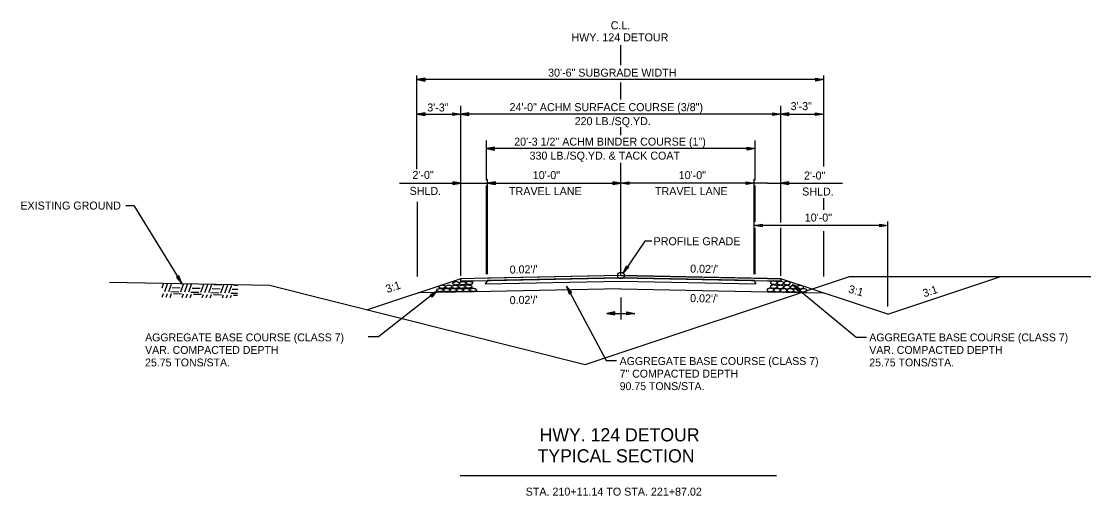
# Model space of a CAD drawing. Extents: x 1824008 to 1828864, y 689441 to 689870.
# Drawn here: x 1828742.7 to 1828822.3, y 689498 to 689533.6 of the extents above; entities that cross this region are included whole.
import ezdxf

# ---------------------------------------------------------------- set-up
doc = ezdxf.new("R2010")
doc.units = 0
for name, color, linetype in [('1', 7, 'Continuous'), ('19', 7, 'Continuous'), ('42', 7, 'Continuous'), ('Level 1', 7, 'Continuous'), ('R_Draft', 7, 'Continuous'), ('R_Horz Alg', 7, 'Continuous')]:
    doc.layers.add(name, color=color, linetype=linetype)

# ---------------------------------------------------------------- blocks, each defined once
blk = doc.blocks.new('ROCKS')
at = {"layer": '1'}
blk.add_spline([(0.013, 0.06), (0.053, 0.053), (0.107, 0.033), (0.133, 0.013), (0.133, -0.007), (0.12, -0.033), (0.107, -0.04), (0.073, -0.053), (0.033, -0.067), (0.013, -0.067), (-0.02, -0.06), (-0.06, -0.053), (-0.087, -0.047), (-0.113, -0.02), (-0.113, -0.007), (-0.107, 0.02), (-0.087, 0.033), (-0.067, 0.047), (-0.033, 0.053), (-0.02, 0.06), (0.013, 0.06)], degree=3, dxfattribs=at)

msp = doc.modelspace()

# ---------------------------------------------------------------- linework, layer by layer
at = {"layer": '1'}
for p, q in [((1828772.928, 689529.296), (1828772.328, 689529.191)), ((1828772.928, 689529.241), (1828772.488, 689529.206)), ((1828772.928, 689529.086), (1828772.928, 689529.296)), ((1828802.221, 689529.086), (1828802.221, 689529.296)), ((1828802.221, 689529.296), (1828802.821, 689529.191)), ((1828802.221, 689529.241), (1828802.661, 689529.206)), ((1828772.328, 689529.191), (1828772.928, 689529.086)), ((1828772.488, 689529.176), (1828772.928, 689529.136)), ((1828802.821, 689529.191), (1828802.221, 689529.086)), ((1828802.661, 689529.176), (1828802.221, 689529.136)), ((1828772.928, 689526.708), (1828772.328, 689526.603)), ((1828772.328, 689526.603), (1828772.928, 689526.498)), ((1828772.928, 689526.653), (1828772.488, 689526.618)), ((1828772.488, 689526.588), (1828772.928, 689526.548)), ((1828772.928, 689526.498), (1828772.928, 689526.708)), ((1828774.997, 689526.498), (1828774.997, 689526.708)), ((1828774.997, 689526.708), (1828775.597, 689526.603)), ((1828774.997, 689526.653), (1828775.437, 689526.618)), ((1828775.597, 689526.603), (1828774.997, 689526.498)), ((1828775.437, 689526.588), (1828774.997, 689526.548)), ((1828776.197, 689526.708), (1828775.597, 689526.603)), ((1828775.597, 689526.603), (1828776.197, 689526.498)), ((1828776.197, 689526.653), (1828775.757, 689526.618)), ((1828775.757, 689526.588), (1828776.197, 689526.548)), ((1828776.197, 689526.498), (1828776.197, 689526.708)), ((1828798.997, 689526.498), (1828798.997, 689526.708)), ((1828798.997, 689526.708), (1828799.597, 689526.603)), ((1828798.997, 689526.653), (1828799.437, 689526.618)), ((1828799.597, 689526.603), (1828798.997, 689526.498)), ((1828799.437, 689526.588), (1828798.997, 689526.548)), ((1828800.197, 689526.708), (1828799.597, 689526.603)), ((1828799.597, 689526.603), (1828800.197, 689526.498)), ((1828800.197, 689526.653), (1828799.757, 689526.618)), ((1828799.757, 689526.588), (1828800.197, 689526.548)), ((1828800.197, 689526.498), (1828800.197, 689526.708)), ((1828802.189, 689526.498), (1828802.189, 689526.708)), ((1828802.189, 689526.708), (1828802.789, 689526.603)), ((1828802.189, 689526.653), (1828802.629, 689526.618)), ((1828802.789, 689526.603), (1828802.189, 689526.498)), ((1828802.629, 689526.588), (1828802.189, 689526.548)), ((1828778.113, 689524.121), (1828777.513, 689524.016)), ((1828777.513, 689524.016), (1828778.113, 689523.911)), ((1828778.113, 689524.066), (1828777.673, 689524.031)), ((1828777.673, 689524.001), (1828778.113, 689523.961)), ((1828778.113, 689523.911), (1828778.113, 689524.121)), ((1828797.059, 689523.911), (1828797.059, 689524.121)), ((1828797.059, 689524.121), (1828797.659, 689524.016)), ((1828797.059, 689524.066), (1828797.499, 689524.031)), ((1828797.659, 689524.016), (1828797.059, 689523.911)), ((1828797.499, 689524.001), (1828797.059, 689523.961)), ((1828774.997, 689521.533), (1828774.997, 689521.323)), ((1828775.597, 689521.428), (1828774.997, 689521.533)), ((1828775.437, 689521.443), (1828774.997, 689521.478)), ((1828774.997, 689521.323), (1828775.597, 689521.428)), ((1828774.997, 689521.373), (1828775.437, 689521.413)), ((1828776.597, 689521.428), (1828787.597, 689521.428)), ((1828777.597, 689514.598), (1828777.597, 689521.728)), ((1828778.197, 689521.533), (1828777.597, 689521.428)), ((1828777.597, 689521.428), (1828787.597, 689521.428)), ((1828777.597, 689521.428), (1828778.197, 689521.323)), ((1828778.197, 689521.478), (1828777.757, 689521.443)), ((1828777.757, 689521.413), (1828778.197, 689521.373)), ((1828778.197, 689521.323), (1828778.197, 689521.533)), ((1828786.997, 689521.533), (1828786.997, 689521.323)), ((1828787.597, 689521.428), (1828786.997, 689521.533)), ((1828786.997, 689521.533), (1828786.997, 689521.323)), ((1828787.597, 689521.428), (1828786.997, 689521.533)), ((1828787.437, 689521.443), (1828786.997, 689521.478)), ((1828787.437, 689521.443), (1828786.997, 689521.478)), ((1828786.997, 689521.323), (1828787.597, 689521.428)), ((1828786.997, 689521.323), (1828787.597, 689521.428)), ((1828786.997, 689521.373), (1828787.437, 689521.413)), ((1828786.997, 689521.373), (1828787.437, 689521.413)), ((1828787.597, 689521.428), (1828788.197, 689521.533)), ((1828787.597, 689521.428), (1828788.197, 689521.533)), ((1828797.597, 689521.428), (1828787.597, 689521.428)), ((1828788.197, 689521.323), (1828787.597, 689521.428)), ((1828797.597, 689521.428), (1828787.597, 689521.428)), ((1828788.197, 689521.323), (1828787.597, 689521.428)), ((1828798.597, 689521.428), (1828787.597, 689521.428)), ((1828787.757, 689521.443), (1828788.197, 689521.478)), ((1828787.757, 689521.443), (1828788.197, 689521.478)), ((1828788.197, 689521.373), (1828787.757, 689521.413)), ((1828788.197, 689521.373), (1828787.757, 689521.413)), ((1828788.197, 689521.533), (1828788.197, 689521.323)), ((1828788.197, 689521.533), (1828788.197, 689521.323)), ((1828796.997, 689521.323), (1828796.997, 689521.533)), ((1828796.997, 689521.533), (1828797.597, 689521.428)), ((1828796.997, 689521.478), (1828797.437, 689521.443)), ((1828797.597, 689521.428), (1828796.997, 689521.323)), ((1828797.437, 689521.413), (1828796.997, 689521.373)), ((1828797.597, 689514.598), (1828797.597, 689521.728)), ((1828800.197, 689521.534), (1828799.597, 689521.429)), ((1828799.597, 689521.429), (1828800.197, 689521.324)), ((1828800.197, 689521.479), (1828799.757, 689521.444)), ((1828799.757, 689521.414), (1828800.197, 689521.374)), ((1828800.197, 689521.324), (1828800.197, 689521.534)), ((1828797.597, 689518.249), (1828798.197, 689518.354)), ((1828798.197, 689518.144), (1828797.597, 689518.249)), ((1828807.325, 689518.249), (1828797.597, 689518.249)), ((1828797.757, 689518.264), (1828798.197, 689518.299)), ((1828798.197, 689518.194), (1828797.757, 689518.234)), ((1828798.197, 689518.354), (1828798.197, 689518.144)), ((1828806.997, 689518.144), (1828806.997, 689518.354)), ((1828806.997, 689518.354), (1828807.597, 689518.249)), ((1828806.997, 689518.299), (1828807.437, 689518.264)), ((1828807.597, 689518.249), (1828806.997, 689518.144)), ((1828807.437, 689518.234), (1828806.997, 689518.194)), ((1828775.597, 689514.258), (1828768.594, 689511.923)), ((1828777.6, 689514.298), (1828775.601, 689514.258)), ((1828787.597, 689514.498), (1828777.6, 689514.298)), ((1828784.922, 689507.817), (1828804.735, 689514.422)), ((1828787.597, 689514.498), (1828797.596, 689514.298)), ((1828797.596, 689514.298), (1828799.596, 689514.258)), ((1828807.597, 689511.591), (1828799.597, 689514.258)), ((1828804.735, 689514.422), (1828834.812, 689514.422)), ((1828807.597, 689511.591), (1828816.088, 689514.422)), ((1828749.258, 689514.008), (1828761.258, 689513.768)), ((1828787.597, 689513.498), (1828776.597, 689513.278)), ((1828787.597, 689513.498), (1828798.597, 689513.278)), ((1828776.597, 689513.278), (1828772.406, 689513.194)), ((1828798.598, 689513.278), (1828802.789, 689513.194)), ((1828775.544, 689499.485), (1828799.256, 689499.485))]:
    msp.add_line(p, q, dxfattribs=at)
msp.add_lwpolyline([(1828761.258, 689513.768), (1828784.922, 689507.817)], dxfattribs=at)
msp.add_circle((1828787.602, 689514.496), 0.25, dxfattribs=at)
at = {"layer": '19'}
for p, q in [((1828772.312, 689522.47), (1828772.312, 689529.499)), ((1828802.805, 689522.669), (1828802.805, 689529.499)), ((1828802.821, 689529.191), (1828772.328, 689529.191)), ((1828775.597, 689514.483), (1828775.597, 689527.22)), ((1828799.597, 689518.474), (1828799.597, 689527.22)), ((1828799.597, 689526.603), (1828775.597, 689526.603)), ((1828777.513, 689521.653), (1828777.513, 689524.632)), ((1828797.659, 689521.653), (1828797.659, 689524.632)), ((1828797.659, 689524.016), (1828777.513, 689524.016)), ((1828772.328, 689520.017), (1828772.328, 689514.434)), ((1828802.789, 689520.302), (1828802.789, 689519.421)), ((1828802.789, 689517.819), (1828802.789, 689514.434)), ((1828775.635, 689514.26), (1828775.55, 689514.091)), ((1828775.55, 689514.091), (1828776.601, 689514.111)), ((1828776.597, 689514.278), (1828775.635, 689514.26)), ((1828787.597, 689514.498), (1828776.597, 689514.278)), ((1828776.601, 689514.111), (1828787.601, 689514.331)), ((1828777.597, 689514.131), (1828777.43, 689513.88)), ((1828777.597, 689514.131), (1828777.43, 689513.88)), ((1828787.601, 689514.331), (1828777.597, 689514.131)), ((1828798.597, 689514.278), (1828787.597, 689514.498)), ((1828787.601, 689514.331), (1828798.594, 689514.111)), ((1828797.597, 689514.131), (1828787.601, 689514.331)), ((1828797.597, 689514.131), (1828797.724, 689513.873)), ((1828797.721, 689513.879), (1828797.597, 689514.131)), ((1828798.594, 689514.111), (1828799.636, 689514.091)), ((1828799.552, 689514.259), (1828798.597, 689514.278)), ((1828799.636, 689514.091), (1828799.552, 689514.259)), ((1828773.839, 689513.341), (1828769.419, 689509.888)), ((1828773.839, 689513.341), (1828773.309, 689513.042)), ((1828773.442, 689512.879), (1828773.839, 689513.341)), ((1828777.43, 689513.88), (1828787.589, 689514.081)), ((1828783.521, 689513.691), (1828786.5, 689508.123)), ((1828783.91, 689513.222), (1828783.521, 689513.691)), ((1828783.521, 689513.691), (1828783.727, 689513.118)), ((1828783.588, 689513.545), (1828783.771, 689513.143)), ((1828783.862, 689513.195), (1828783.614, 689513.559)), ((1828787.589, 689514.081), (1828787.597, 689514.081)), ((1828787.597, 689514.081), (1828787.606, 689514.081)), ((1828787.606, 689514.081), (1828797.721, 689513.879)), ((1828800.454, 689513.815), (1828805.23, 689509.882)), ((1828800.983, 689513.514), (1828800.454, 689513.815)), ((1828800.454, 689513.815), (1828800.849, 689513.352)), ((1828800.567, 689513.702), (1828800.881, 689513.391)), ((1828800.948, 689513.472), (1828800.587, 689513.725)), ((1828800.849, 689513.352), (1828800.983, 689513.514)), ((1828773.309, 689513.042), (1828773.442, 689512.879)), ((1828773.706, 689513.251), (1828773.34, 689513.003)), ((1828773.407, 689512.922), (1828773.725, 689513.228)), ((1828783.727, 689513.118), (1828783.91, 689513.222)), ((1828769.419, 689509.888), (1828768.653, 689509.888)), ((1828805.23, 689509.882), (1828805.996, 689509.882)), ((1828786.5, 689508.123), (1828787.266, 689508.123))]:
    msp.add_line(p, q, dxfattribs=at)
for points in [[(1828787.589, 689514.081), (1828787.589, 689514.081)], [(1828787.606, 689514.081), (1828787.606, 689514.081)]]:
    msp.add_lwpolyline(points, dxfattribs=at)
at = {"layer": '42'}
for p, q in [((1828753.205, 689513.574), (1828753.315, 689513.877)), ((1828753.412, 689513.308), (1828753.614, 689513.867)), ((1828753.712, 689513.3), (1828753.913, 689513.858)), ((1828753.861, 689513.296), (1828754.461, 689513.281)), ((1828753.969, 689513.594), (1828754.569, 689513.579)), ((1828754.611, 689513.278), (1828754.816, 689513.845)), ((1828754.911, 689513.27), (1828755.118, 689513.843)), ((1828755.211, 689513.262), (1828755.421, 689513.842)), ((1828755.469, 689513.556), (1828756.068, 689513.541)), ((1828756.111, 689513.24), (1828756.326, 689513.835)), ((1828756.173, 689513.838), (1828756.176, 689513.838)), ((1828756.411, 689513.232), (1828756.626, 689513.827)), ((1828756.711, 689513.225), (1828756.926, 689513.82)), ((1828756.968, 689513.518), (1828757.568, 689513.503)), ((1828757.076, 689513.816), (1828757.675, 689513.801)), ((1828757.61, 689513.202), (1828757.825, 689513.797)), ((1828757.91, 689513.195), (1828758.125, 689513.789)), ((1828758.21, 689513.187), (1828758.425, 689513.782)), ((1828758.468, 689513.481), (1828758.878, 689513.47)), ((1828758.575, 689513.778), (1828758.886, 689513.77)), ((1828753.207, 689512.88), (1828753.308, 689513.16)), ((1828753.506, 689512.87), (1828753.608, 689513.153)), ((1828753.805, 689512.861), (1828753.908, 689513.145)), ((1828754.058, 689513.141), (1828754.657, 689513.126)), ((1828754.707, 689512.845), (1828754.807, 689513.123)), ((1828755.009, 689512.844), (1828755.107, 689513.115)), ((1828755.311, 689512.843), (1828755.407, 689513.108)), ((1828755.361, 689513.259), (1828755.961, 689513.244)), ((1828755.557, 689513.104), (1828756.107, 689513.09)), ((1828756.107, 689513.09), (1828756.157, 689513.089)), ((1828756.218, 689512.838), (1828756.307, 689513.085)), ((1828756.52, 689512.837), (1828756.607, 689513.077)), ((1828756.822, 689512.836), (1828756.907, 689513.07)), ((1828756.861, 689513.221), (1828757.46, 689513.206)), ((1828757.057, 689513.066), (1828757.657, 689513.051)), ((1828757.729, 689512.832), (1828757.806, 689513.047)), ((1828758.032, 689512.834), (1828758.106, 689513.04)), ((1828758.338, 689512.844), (1828758.406, 689513.032)), ((1828758.36, 689513.183), (1828758.87, 689513.17)), ((1828758.556, 689513.028), (1828758.867, 689513.02)), ((1828787.597, 689512.838), (1828787.597, 689511.205)), ((1828787.15, 689511.762), (1828786.55, 689511.657)), ((1828787.15, 689511.707), (1828786.71, 689511.672)), ((1828787.15, 689511.552), (1828787.15, 689511.762)), ((1828788.045, 689511.552), (1828788.045, 689511.762)), ((1828788.045, 689511.762), (1828788.645, 689511.657)), ((1828788.045, 689511.707), (1828788.485, 689511.672)), ((1828786.55, 689511.657), (1828787.15, 689511.552)), ((1828786.55, 689511.657), (1828788.645, 689511.657)), ((1828786.71, 689511.642), (1828787.15, 689511.602)), ((1828788.645, 689511.657), (1828788.045, 689511.552)), ((1828788.485, 689511.642), (1828788.045, 689511.602))]:
    msp.add_line(p, q, dxfattribs=at)
at = {"layer": 'R_Draft'}
for p, q in [((1828787.597, 689530.282), (1828787.597, 689531.77)), ((1828787.597, 689527.708), (1828787.597, 689528.977)), ((1828772.328, 689526.603), (1828775.597, 689526.603)), ((1828799.597, 689526.603), (1828802.789, 689526.603)), ((1828787.597, 689525.036), (1828787.597, 689525.62)), ((1828799.597, 689525.127), (1828799.597, 689525.62)), ((1828787.597, 689514.498), (1828787.597, 689522.96)), ((1828770.993, 689521.428), (1828776.597, 689521.428)), ((1828777.597, 689521.428), (1828787.597, 689521.428)), ((1828786.997, 689521.533), (1828786.997, 689521.323)), ((1828787.597, 689521.428), (1828786.997, 689521.533)), ((1828787.437, 689521.443), (1828786.997, 689521.478)), ((1828786.997, 689521.323), (1828787.597, 689521.428)), ((1828786.997, 689521.373), (1828787.437, 689521.413)), ((1828787.597, 689521.428), (1828788.197, 689521.533)), ((1828797.597, 689521.428), (1828787.597, 689521.428)), ((1828788.197, 689521.323), (1828787.597, 689521.428)), ((1828787.757, 689521.443), (1828788.197, 689521.478)), ((1828788.197, 689521.373), (1828787.757, 689521.413)), ((1828788.197, 689521.533), (1828788.197, 689521.323)), ((1828798.597, 689521.428), (1828804.218, 689521.428)), ((1828787.779, 689514.672), (1828788.026, 689515.229)), ((1828788.199, 689515.112), (1828787.779, 689514.672)), ((1828787.859, 689514.81), (1828788.068, 689515.195)), ((1828788.159, 689515.135), (1828787.881, 689514.798)), ((1828788.026, 689515.229), (1828788.199, 689515.112)), ((1828754.458, 689514.466), (1828754.28, 689514.357)), ((1828754.28, 689514.357), (1828754.682, 689513.9)), ((1828754.321, 689514.378), (1828754.585, 689514.029)), ((1828754.608, 689514.041), (1828754.415, 689514.434)), ((1828754.682, 689513.9), (1828754.458, 689514.466))]:
    msp.add_line(p, q, dxfattribs=at)
for points in [[(1828750.487, 689519.744), (1828751.087, 689519.744), (1828754.682, 689513.9)], [(1828789.915, 689517.068), (1828789.383, 689517.068), (1828787.779, 689514.672)]]:
    msp.add_lwpolyline(points, dxfattribs=at)
at = {"layer": 'R_Horz Alg'}
for p, q in [((1828777.513, 689514.598), (1828777.513, 689521.247)), ((1828797.659, 689518.53), (1828797.659, 689521.247)), ((1828797.659, 689514.598), (1828797.659, 689518.078)), ((1828799.597, 689514.485), (1828799.597, 689518.078)), ((1828807.597, 689512.172), (1828807.597, 689518.549))]:
    msp.add_line(p, q, dxfattribs=at)

# ---------------------------------------------------------------- block references
at = {"layer": 'Level 1'}
for p, xscale, yscale, rotation in [((1828799.044, 689513.966), 2.0116542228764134, 2.0116542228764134, 0.3302009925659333), ((1828774.069, 689513.41), 2.011654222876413, -2.011654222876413, 178.81230068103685), ((1828774.208, 689513.664), 2.011654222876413, -2.011654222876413, 178.81230068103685), ((1828774.551, 689513.414), 2.011654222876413, -2.011654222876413, 178.81230068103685), ((1828774.699, 689513.665), 2.011654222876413, -2.011654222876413, 178.81230068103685), ((1828775.042, 689513.415), 2.011654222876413, -2.011654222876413, 178.81230068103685), ((1828775.202, 689513.653), 2.011654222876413, -2.011654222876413, 178.81230068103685), ((1828775.263, 689513.917), 2.011654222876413, -2.011654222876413, 178.81230068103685), ((1828775.545, 689513.403), 2.011654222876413, -2.011654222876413, 178.81230068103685), ((1828775.698, 689513.662), 2.011654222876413, -2.011654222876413, 178.81230068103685), ((1828775.759, 689513.926), 2.011654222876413, -2.011654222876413, 178.81230068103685), ((1828776.042, 689513.412), 2.011654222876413, -2.011654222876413, 178.81230068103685), ((1828776.19, 689513.681), 2.011654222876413, -2.011654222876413, 178.81230068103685), ((1828776.261, 689513.946), 2.011654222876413, -2.011654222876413, 178.81230068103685), ((1828776.538, 689513.424), 2.011654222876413, -2.011654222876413, 178.81230068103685), ((1828798.787, 689513.424), 2.0116542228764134, 2.0116542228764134, 0.3302009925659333), ((1828799.04, 689513.674), 2.0116542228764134, 2.0116542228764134, 0.3302009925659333), ((1828799.283, 689513.404), 2.0116542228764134, 2.0116542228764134, 0.3302009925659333), ((1828799.531, 689513.934), 2.0116542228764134, 2.0116542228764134, 0.3302009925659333), ((1828799.531, 689513.647), 2.0116542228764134, 2.0116542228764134, 0.3302009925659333), ((1828799.779, 689513.388), 2.0116542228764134, 2.0116542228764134, 0.3302009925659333), ((1828800.027, 689513.631), 2.0116542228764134, 2.0116542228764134, 0.3302009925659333), ((1828800.031, 689513.934), 2.0116542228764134, 2.0116542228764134, 0.3302009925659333), ((1828800.282, 689513.393), 2.0116542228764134, 2.0116542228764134, 0.3302009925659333), ((1828800.53, 689513.636), 2.0116542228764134, 2.0116542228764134, 0.3302009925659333), ((1828800.773, 689513.385), 2.0116542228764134, 2.0116542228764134, 0.3302009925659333), ((1828801.021, 689513.627), 2.0116542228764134, 2.0116542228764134, 0.3302009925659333), ((1828801.274, 689513.387), 2.0116542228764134, 2.0116542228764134, 0.3302009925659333)]:
    msp.add_blockref('ROCKS', p, dxfattribs=dict(at, xscale=xscale, yscale=yscale, rotation=rotation))

# ---------------------------------------------------------------- texts
at = {"layer": '1'}
for s, height, rotation, p in [('C.L.', 0.6, 360, (1828786.836, 689532.964)), ('HWY. 124 DETOUR', 0.6, 360, (1828783.89, 689532.064)), ("0.02'/'", 0.6, 1.14576, (1828779.267, 689514.64)), ("0.02'/'", 0.6, 358.85424, (1828792.782, 689514.719)), ("0.02'/'", 0.6, 358.85424, (1828792.782, 689514.719)), ('3:1', 0.6, 18.43495, (1828770.086, 689513.184)), ('3:1', 0.6, 344.22515, (1828804.607, 689513.226)), ('3:1', 0.6, 18.43495, (1828810.342, 689512.856)), ("0.02'/'", 0.6, 1.14576, (1828779.267, 689512.348)), ("0.02'/'", 0.6, 358.85424, (1828792.782, 689512.507)), ('HWY. 124 DETOUR', 0.98999, 359.99538, (1828781.505, 689502.057)), ('TYPICAL SECTION ', 0.98999, 359.99538, (1828781.349, 689500.473))]:
    msp.add_text(s, height=height, rotation=rotation, dxfattribs=at).set_placement(p)
for s, p in [('30\'-6" SUBGRADE WIDTH', (1828782.141, 689529.416)), ('24\'-0" ACHM SURFACE COURSE (3/8")', (1828779.254, 689526.828)), ('220 LB./SQ.YD.', (1828784.134, 689525.778)), ('20\'-3 1/2" ACHM BINDER COURSE (1")', (1828779.597, 689524.241)), ('330 LB./SQ.YD. & TACK COAT', (1828780.752, 689523.191)), ('SHLD.', (1828801.188, 689520.499))]:
    msp.add_text(s, height=0.6, dxfattribs=at).set_placement(p)
at = {"layer": '19'}
for s, p in [('AGGREGATE BASE COURSE (CLASS 7)', (1828751.938, 689509.561)), ('AGGREGATE BASE COURSE (CLASS 7)', (1828806.218, 689509.561)), ('VAR. COMPACTED DEPTH', (1828751.938, 689508.621)), ('VAR. COMPACTED DEPTH', (1828806.218, 689508.621)), ('25.75 TONS/STA.', (1828751.938, 689507.681)), ('AGGREGATE BASE COURSE (CLASS 7)', (1828787.508, 689507.784)), ('25.75 TONS/STA.', (1828806.218, 689507.681)), ('7" COMPACTED DEPTH', (1828787.508, 689506.844)), ('90.75 TONS/STA.', (1828787.508, 689505.904))]:
    msp.add_text(s, height=0.59001, rotation=360, dxfattribs=at).set_placement(p)
at = {"layer": 'R_Draft'}
for s, p in [('3\'-3"', (1828773.083, 689526.804)), ('3\'-3"', (1828800.322, 689526.903)), ('10\'-0"', (1828791.934, 689521.728)), ('2\'-0"', (1828801.326, 689521.699)), ('TRAVEL LANE', (1828790.156, 689520.528)), ('EXISTING GROUND', (1828742.585, 689519.444)), ('10\'-0"', (1828801.382, 689518.549))]:
    msp.add_text(s, height=0.6, dxfattribs=at).set_placement(p)
for s, rotation, p in [('2\'-0"', 360, (1828771.969, 689521.746)), ('10\'-0"', 360, (1828780.995, 689521.728)), ('SHLD.', 360, (1828771.761, 689520.546)), ('TRAVEL LANE', 360, (1828779.216, 689520.528)), ('PROFILE GRADE', 360, (1828790.051, 689516.768)), ('STA. 210+11.14 TO STA. 221+87.02', 359.99538, (1828780.463, 689497.986))]:
    msp.add_text(s, height=0.6, rotation=rotation, dxfattribs=at).set_placement(p)

doc.saveas('drawing.dxf')
